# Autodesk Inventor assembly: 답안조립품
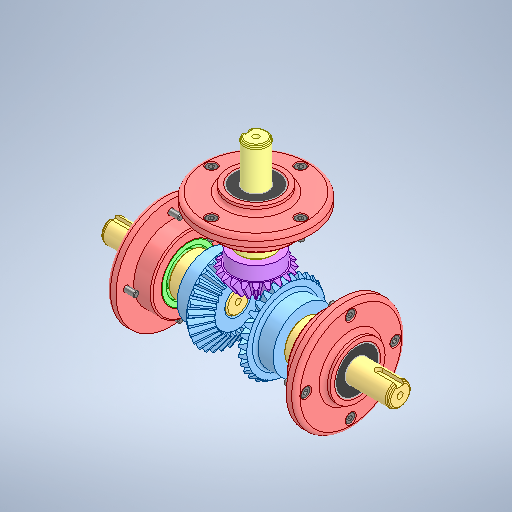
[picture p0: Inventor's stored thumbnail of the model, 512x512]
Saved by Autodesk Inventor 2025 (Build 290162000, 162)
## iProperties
Created: 2026-07
Part Number: 답안조립품
Document SubType Name: Assembly
Designer: KDI
Author: KDI
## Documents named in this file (12)
- C:\Users\KDI\Desktop\760703V1009\답안조립품.iam
- C:\Users\KDI\Desktop\760703V1009\1-본체.ipt
- C:\Users\KDI\Desktop\760703V1009\6각 구멍붙이 볼트 M4x10\6각 구멍붙이 볼트 M4x10.ipt
- C:\Users\KDI\Desktop\760703V1009\깊은 홈 볼 베어링 6203\깊은 홈 볼 베어링 6203.ipt
- C:\Users\KDI\Desktop\760703V1009\메인 베벨기어\메인 베벨기어.ipt
- C:\Users\KDI\Desktop\760703V1009\메인 축\메인 축.ipt
- C:\Users\KDI\Desktop\760703V1009\서브 베벨기어\서브 베벨기어.ipt
- C:\Users\KDI\Desktop\760703V1009\서브 축\서브 축.ipt
- C:\Users\KDI\Desktop\760703V1009\오일 실 17 32 8\오일 실 17 32 8.ipt
- C:\Users\KDI\Desktop\760703V1009\커버\커버.ipt
- C:\Users\KDI\Desktop\760703V1009\평행 키 4x4x14\평행 키 4x4x14.ipt
- C:\Users\KDI\Desktop\760703V1009\평행 키 5x5x14\평행 키 5x5x14.ipt
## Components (13 placed, 2 different names)
1. 1-본체:1
2. 6각 구멍붙이 볼트 M4x10:1
3. 6각 구멍붙이 볼트 M4x10:4
4. 6각 구멍붙이 볼트 M4x10:5
5. 6각 구멍붙이 볼트 M4x10:6
6. 6각 구멍붙이 볼트 M4x10:3
7. 6각 구멍붙이 볼트 M4x10:7
8. 6각 구멍붙이 볼트 M4x10:8
9. 6각 구멍붙이 볼트 M4x10:9
10. 6각 구멍붙이 볼트 M4x10:2
11. 6각 구멍붙이 볼트 M4x10:10
12. 6각 구멍붙이 볼트 M4x10:11
13. 6각 구멍붙이 볼트 M4x10:12
